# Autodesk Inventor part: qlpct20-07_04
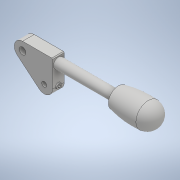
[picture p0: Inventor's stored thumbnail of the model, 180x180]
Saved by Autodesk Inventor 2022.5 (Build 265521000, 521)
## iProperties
Part Number: qlpct20-07_04
Material: 一般
Document SubType Name: Modeling
Designer: ImaoCorp
Density: 1 g/cm^3
Appearance: 既定
Author: ImaoCorp
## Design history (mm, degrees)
feature "qlpct20-07_04"
node "ソリッド1"
